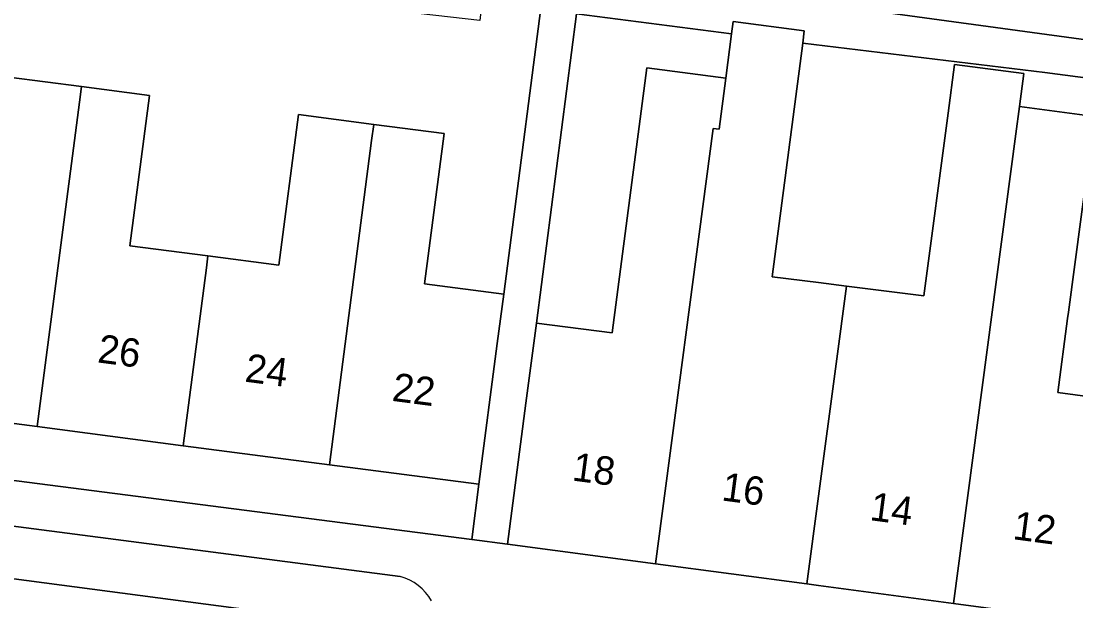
# Model space of a CAD drawing. Extents: x 161838 to 162344, y 381620 to 382160.
# Drawn here: x 161971.89 to 162009.08, y 381703.98 to 381724.41 of the extents above; entities that cross this region are included whole.
import ezdxf

# ---------------------------------------------------------------- set-up
doc = ezdxf.new("R2010")
doc.units = 0
for name, color, linetype in [('IMGEO_Erf', 7, 'Continuous'), ('IMGEO_Pand', 7, 'Continuous'), ('IMGEO_Pand_nummerreeks', 7, 'Continuous'), ('IMGEO_Parkeervlak_open', 7, 'Continuous'), ('IMGEO_Rijbaan_lokaal_open', 7, 'Continuous'), ('IMGEO_Voetpad_open', 7, 'Continuous')]:
    doc.layers.add(name, color=color, linetype=linetype)

msp = doc.modelspace()

# ---------------------------------------------------------------- linework, layer by layer
at = {"layer": 'IMGEO_Erf'}
for points in [[(161971.448, 381722.434), (161974.011, 381722.1), (161976.41, 381721.787), (161975.72, 381716.496), (161978.474, 381716.137), (161980.971, 381715.811), (161981.663, 381721.117), (161984.319, 381720.77), (161986.802, 381720.446), (161986.112, 381715.156), (161988.901, 381714.793), (161990.474, 381726.878), (161988.362, 381727.119), (161988.055, 381724.426), (161984.846, 381724.791), (161980.529, 381725.282), (161980.881, 381728.381), (161978.103, 381728.872), (161977.75, 381725.774), (161974.539, 381726.139), (161970.224, 381726.63)], [(162012.365, 381722.027), (162007.983, 381722.598), (161999.444, 381723.63), (161998.371, 381715.405), (162000, 381715.198), (162000.991, 381715.072), (162003.709, 381714.726), (162004.567, 381721.164), (162004.796, 381722.881), (162007.243, 381722.562), (162007.089, 381721.399), (162009.728, 381721.048), (162008.809, 381714.15), (162008.78, 381713.936), (162008.433, 381711.329), (162010.711, 381711.025)], [(161956.476, 381710.172), (161987.777, 381706.147), (161988.027, 381708.09), (161982.754, 381708.778), (161977.601, 381709.45), (161972.448, 381710.122), (161967.295, 381710.794)]]:
    msp.add_lwpolyline(points, dxfattribs=at)
msp.add_lwpolyline([(161993.945, 381722.758), (161996.728, 381722.396), (161996.932, 381723.958), (161991.473, 381724.669), (161990.054, 381713.77), (161992.728, 381713.422), (161993.711, 381720.964)], close=True, dxfattribs=at)
at = {"layer": 'IMGEO_Pand'}
for points in [[(162024.059, 381736.377), (162003.547, 381745.723), (162000, 381747.039), (161998.107, 381744.019), (161997.212, 381744.268), (161992.167, 381726.115), (162012.543, 381723.321), (162017.783, 381722.602)], [(162000.991, 381715.072), (162000, 381715.198), (161998.371, 381715.405), (161999.444, 381723.63), (161999.5, 381724.063), (161996.988, 381724.391), (161996.932, 381723.958), (161996.728, 381722.396), (161996.494, 381720.602), (161996.286, 381720.629), (161994.25, 381705.292), (161999.589, 381704.582), (162000, 381707.674), (162000.627, 381712.34)], [(161996.728, 381722.396), (161993.945, 381722.758), (161993.711, 381720.964), (161992.728, 381713.422), (161990.054, 381713.77), (161989.686, 381710.944), (161989.039, 381705.985), (161994.25, 381705.292), (161996.286, 381720.629), (161996.494, 381720.602)], [(162007.089, 381721.399), (162007.243, 381722.562), (162004.796, 381722.881), (162004.567, 381721.164), (162003.709, 381714.726), (162000.991, 381715.072), (162000.627, 381712.34), (162000, 381707.674), (161999.589, 381704.582), (162000, 381704.527), (162004.764, 381703.893), (162006.961, 381720.438)], [(161967.295, 381710.794), (161972.448, 381710.122), (161973.94, 381721.553), (161974.011, 381722.1), (161971.448, 381722.434), (161970.769, 381717.223), (161968.178, 381717.561), (161968.113, 381717.061)], [(161974.011, 381722.1), (161973.94, 381721.553), (161972.448, 381710.122), (161977.601, 381709.45), (161978.419, 381715.714), (161978.474, 381716.137), (161975.72, 381716.496), (161976.41, 381721.787)], [(162007.089, 381721.399), (162006.961, 381720.438), (162004.764, 381703.893), (162009.676, 381703.239), (162010.711, 381711.025), (162008.433, 381711.329), (162008.78, 381713.936), (162008.809, 381714.15), (162009.728, 381721.048)], [(161982.754, 381708.778), (161984.245, 381720.205), (161984.319, 381720.77), (161981.663, 381721.117), (161980.971, 381715.811), (161978.474, 381716.137), (161978.419, 381715.714), (161977.601, 381709.45)], [(161982.754, 381708.778), (161988.027, 381708.09), (161988.674, 381713.049), (161988.901, 381714.793), (161986.112, 381715.156), (161986.802, 381720.446), (161984.319, 381720.77), (161984.245, 381720.205)]]:
    msp.add_lwpolyline(points, close=True, dxfattribs=at)
at = {"layer": 'IMGEO_Parkeervlak_open'}
for points in [[(161985.254, 381704.84), (161959.136, 381708.231)], [(161955.508, 381706.888), (161956.834, 381706.713), (161986.241, 381702.838), (161988.01, 381702.605)]]:
    msp.add_lwpolyline(points, dxfattribs=at)
msp.add_arc((161984.809, 381703.139), 1.758, 28.7211, 75.3483, dxfattribs=at)
at = {"layer": 'IMGEO_Rijbaan_lokaal_open'}
msp.add_lwpolyline([(161956.834, 381706.713), (161956.395, 381703.427), (161985.793, 381699.532), (161986.241, 381702.838)], close=True, dxfattribs=at)
at = {"layer": 'IMGEO_Voetpad_open'}
for points in [[(161990.474, 381726.878), (161988.901, 381714.793), (161988.674, 381713.049), (161988.027, 381708.09), (161987.777, 381706.147), (161989.039, 381705.985), (161989.686, 381710.944), (161990.054, 381713.77), (161991.473, 381724.669), (161996.932, 381723.958), (161996.988, 381724.391), (161999.5, 381724.063), (161999.444, 381723.63), (162007.983, 381722.598), (162012.365, 381722.027), (162012.543, 381723.321), (161992.167, 381726.115)], [(162052.602, 381697.712), (162049.351, 381697.959), (162041.781, 381698.968), (162035.43, 381699.815), (162034.419, 381699.947), (162028.849, 381700.688), (162023.552, 381701.393), (162018.578, 381702.055), (162009.676, 381703.239), (162004.764, 381703.893), (162000, 381704.527), (161999.589, 381704.582), (161994.25, 381705.292), (161989.039, 381705.985), (161987.777, 381706.147), (161956.476, 381710.172), (161955.308, 381710.322), (161949.883, 381711.029), (161944.702, 381711.705), (161939.487, 381712.385), (161934.405, 381713.048)], [(161959.136, 381708.231), (161985.254, 381704.84)]]:
    msp.add_lwpolyline(points, dxfattribs=at)
msp.add_arc((161984.809, 381703.139), 1.758, 28.7211, 75.3483, dxfattribs=at)

# ---------------------------------------------------------------- texts
at = {"layer": 'IMGEO_Pand_nummerreeks'}
for s, rotation, p in [('26', 352.5703, (161974.552, 381712.389)), ('24', 352.5703, (161979.745, 381711.711)), ('22', 352.5703, (161984.935, 381711.034)), ('18', 352.4198, (161991.283, 381708.229)), ('16', 352.4198, (161996.555, 381707.527)), ('14', 352.4255, (162001.78, 381706.832)), ('12', 352.4198, (162006.821, 381706.162))]:
    msp.add_text(s, height=1, rotation=rotation, dxfattribs=at).set_placement(p)

doc.saveas('drawing.dxf')
